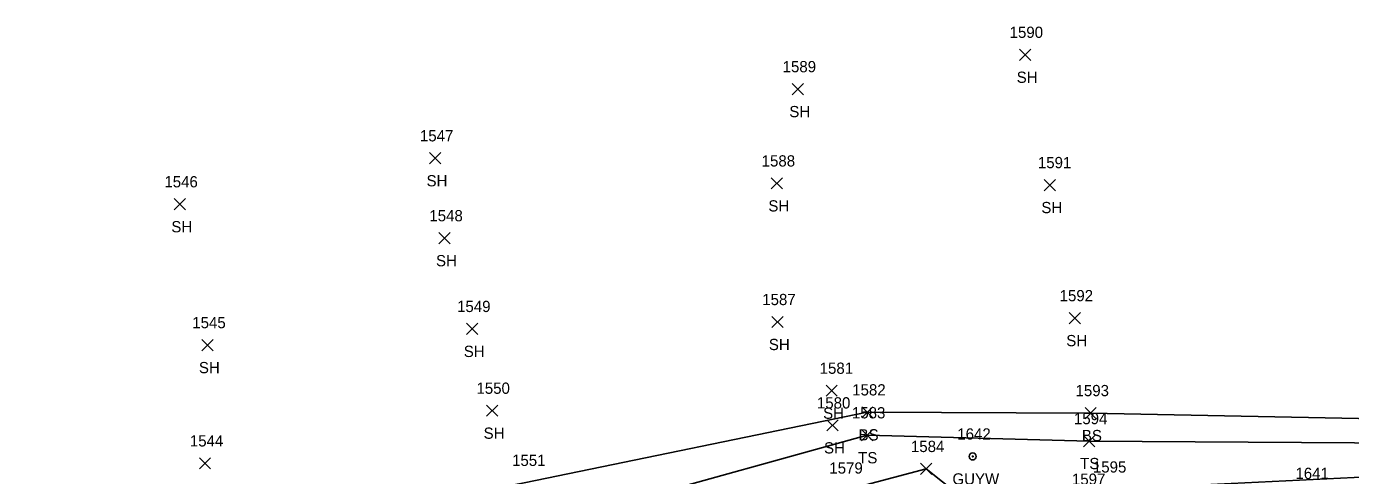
# Model space of a CAD drawing. Extents: x 1497084 to 1499861, y 734741 to 735567.
# Drawn here: x 1499123.3 to 1499358.9, y 735487.1 to 735567 of the extents above; entities that cross this region are included whole.
import ezdxf

# ---------------------------------------------------------------- set-up
doc = ezdxf.new("R2010")
doc.units = 0
for name, color, linetype in [('L_A', 7, 'Continuous'), ('L_I', 7, 'Continuous'), ('L_TIC', 7, 'Continuous'), ('LELB', 7, 'Continuous'), ('S_I', 7, 'Continuous'), ('U_A', 7, 'Continuous'), ('U_I', 7, 'Continuous'), ('UPGW', 7, 'Continuous')]:
    doc.layers.add(name, color=color, linetype=linetype)

msp = doc.modelspace()

# ---------------------------------------------------------------- linework, layer by layer
at = {"layer": 'L_TIC'}
for points in [[(1499299.99, 735560.96), (1499301.99, 735562.96)], [(1499301.99, 735560.96), (1499299.99, 735562.96)], [(1499259.52, 735554.85), (1499261.52, 735556.85)], [(1499261.52, 735554.85), (1499259.52, 735556.85)], [(1499194.97, 735542.55), (1499196.97, 735544.55)], [(1499196.97, 735542.55), (1499194.97, 735544.55)], [(1499255.79, 735538.08), (1499257.79, 735540.08)], [(1499257.79, 735538.08), (1499255.79, 735540.08)], [(1499304.37, 735537.78), (1499306.37, 735539.78)], [(1499306.37, 735537.78), (1499304.37, 735539.78)], [(1499149.55, 735534.37), (1499151.55, 735536.37)], [(1499151.55, 735534.37), (1499149.55, 735536.37)], [(1499196.65, 735528.33), (1499198.65, 735530.33)], [(1499198.65, 735528.33), (1499196.65, 735530.33)], [(1499308.8, 735514.11), (1499310.8, 735516.11)], [(1499310.8, 735514.11), (1499308.8, 735516.11)], [(1499201.59, 735512.19), (1499203.59, 735514.19)], [(1499203.59, 735512.19), (1499201.59, 735514.19)], [(1499255.89, 735513.42), (1499257.89, 735515.42)], [(1499257.89, 735513.42), (1499255.89, 735515.42)], [(1499154.46, 735509.31), (1499156.46, 735511.31)], [(1499156.46, 735509.31), (1499154.46, 735511.31)], [(1499265.54, 735501.2), (1499267.54, 735503.2)], [(1499267.54, 735501.2), (1499265.54, 735503.2)], [(1499205.12, 735497.64), (1499207.12, 735499.64)], [(1499207.12, 735497.64), (1499205.12, 735499.64)], [(1499271.89, 735497.35), (1499273.89, 735499.35)], [(1499273.89, 735497.35), (1499271.89, 735499.35)], [(1499311.63, 735497.22), (1499313.63, 735499.22)], [(1499313.63, 735497.22), (1499311.63, 735499.22)], [(1499265.7, 735495.03), (1499267.7, 735497.03)], [(1499267.7, 735495.03), (1499265.7, 735497.03)], [(1499271.85, 735493.27), (1499273.85, 735495.27)], [(1499273.85, 735493.27), (1499271.85, 735495.27)], [(1499311.36, 735492.24), (1499313.36, 735494.24)], [(1499313.36, 735492.24), (1499311.36, 735494.24)], [(1499154.03, 735488.27), (1499156.03, 735490.27)], [(1499156.03, 735488.27), (1499154.03, 735490.27)], [(1499282.35, 735487.28), (1499284.35, 735489.28)], [(1499284.35, 735487.28), (1499282.35, 735489.28)]]:
    msp.add_lwpolyline(points, dxfattribs=at)
at = {"layer": 'LELB'}
for points in [[(1498873.92, 735413.56), (1498885.61, 735419.45), (1498937.6, 735431.47), (1498992.42, 735446.17), (1499046.55, 735456.42), (1499100.05, 735466.4), (1499155.3, 735475.02), (1499211.81, 735485.81), (1499272.89, 735498.35), (1499312.63, 735498.22), (1499378.23, 735496.87), (1499423.72, 735498.7), (1499448.77, 735497.16), (1499468.03, 735503.5), (1499479.61, 735506.38), (1499485.8, 735535.79), (1499495.73, 735555.05)], [(1498887.06, 735413.08), (1498886.64, 735416.64), (1498937.22, 735426.43), (1498992.82, 735439.97), (1499047, 735450.43), (1499100.75, 735458.28), (1499155.76, 735466.18), (1499214.75, 735478.18), (1499272.85, 735494.27), (1499312.36, 735493.24), (1499378.42, 735492.78), (1499423.87, 735493.47), (1499447.7, 735493.36), (1499467.98, 735499.39), (1499480.88, 735502.15), (1499491.75, 735532.72), (1499501.47, 735549.91)], [(1498866.36, 735448.26), (1498857.15, 735430.71), (1498857.91, 735411.98), (1498873.92, 735413.56), (1498887.06, 735413.08), (1498937.75, 735422.9), (1498993.01, 735435.64), (1499049.83, 735446.27), (1499101.27, 735455.9), (1499156.57, 735462.9), (1499215.64, 735473.1), (1499268.79, 735480.58), (1499268.83, 735484.45), (1499283.35, 735488.28), (1499292.38, 735481.13), (1499315.72, 735484.63), (1499378.98, 735487.71)]]:
    msp.add_lwpolyline(points, dxfattribs=at)
at = {"layer": 'UPGW'}
for radius in [0.625, 0.0833]:
    msp.add_circle((1499291.64, 735490.5), radius, dxfattribs=at)

# ---------------------------------------------------------------- texts
at = {"layer": 'L_A'}
for s, p in [('SH', (1499299.47, 735556.96)), ('SH', (1499259.01, 735550.85)), ('SH', (1499194.46, 735538.55)), ('SH', (1499255.28, 735534.08)), ('SH', (1499303.86, 735533.78)), ('SH', (1499149.04, 735530.37)), ('SH', (1499196.14, 735524.33)), ('SH', (1499255.37, 735509.42)), ('SH', (1499308.29, 735510.11)), ('SH', (1499201.08, 735508.19)), ('SH', (1499153.95, 735505.31)), ('SH', (1499265.03, 735497.2)), ('SH', (1499204.61, 735493.64)), ('BS', (1499271.33, 735493.35)), ('BS', (1499311.07, 735493.22)), ('SH', (1499265.19, 735491.03)), ('TS', (1499271.26, 735489.27)), ('TS', (1499310.76, 735488.24))]:
    msp.add_text(s, height=2, dxfattribs=at).set_placement(p)
at = {"layer": 'L_I'}
for s, p in [('1590', (1499298.21, 735564.96)), ('1589', (1499257.82, 735558.85)), ('1547', (1499193.28, 735546.55)), ('1588', (1499254.09, 735542.08)), ('1591', (1499303.24, 735541.78)), ('1546', (1499147.81, 735538.37)), ('1548', (1499194.96, 735532.33)), ('1549', (1499199.89, 735516.19)), ('1587', (1499254.19, 735517.42)), ('1592', (1499307.11, 735518.11)), ('1545', (1499152.77, 735513.31)), ('1581', (1499264.41, 735505.2)), ('1550', (1499203.34, 735501.64)), ('1582', (1499270.2, 735501.35)), ('1593', (1499309.94, 735501.22)), ('1580', (1499263.92, 735499.03)), ('1583', (1499270.15, 735497.27)), ('1594', (1499309.66, 735496.24)), ('1544', (1499152.34, 735492.27)), ('1584', (1499280.65, 735491.28)), ('1551', (1499209.68, 735488.81)), ('1579', (1499266.13, 735487.45)), ('1597', (1499309.3, 735485.45)), ('1595', (1499313.03, 735487.63))]:
    msp.add_text(s, height=2, dxfattribs=at).set_placement(p)
at = {"layer": 'S_I'}
msp.add_text('1641', height=2, dxfattribs=at).set_placement((1499349.07, 735486.49))
at = {"layer": 'U_A'}
msp.add_text('GUYW', height=2, dxfattribs=at).set_placement((1499288.04, 735485.5))
at = {"layer": 'U_I'}
msp.add_text('1642', height=2, dxfattribs=at).set_placement((1499288.9, 735493.5))

doc.saveas('drawing.dxf')
